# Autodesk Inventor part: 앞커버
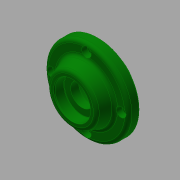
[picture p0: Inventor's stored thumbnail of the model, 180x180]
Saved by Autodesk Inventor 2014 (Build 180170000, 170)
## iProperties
Created: 2017-08
Part Number: 앞커버
Material: 알루미늄 6061
Document SubType Name: Modeling
Designer: mduedu
Density: 1 g/cm^3
Appearance: Dark Green
Author: mduedu
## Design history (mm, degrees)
sketch "스케치1"
  geometry: C1 r 35 at (0, 0); 1 further point
  constraints: 1 centre point, 1 coincident
  dimensions: "d0" = 70 diameter of C1
extrude "돌출1" new body sketch "스케치1" distance "d1" = 10; taper "d2" = 0 deg
sketch "스케치2"
  geometry: C1 r 24 at (0, 0); 1 further point
  constraints: 1 centre point, 1 coincident
  dimensions: "d3" = 48 diameter of C1
node "작업 평면1"
sketch "스케치3"
  geometry: C1 r 20 at (0, 0); 1 further point
  constraints: 1 centre point, 1 coincident
  dimensions: "d5" = 40 diameter of C1
feature "로프트1" sketch "스케치3" dims "d6" = 0, "d7" = 90 deg, "d8" = 0, "d9" = 90 deg
sketch "스케치4"
  geometry: C1 r 24 at (0, 0) reference; 1 further point
extrude "돌출2" join sketch "스케치4" distance "d10" = 8; taper "d11" = 0 deg
hole "구멍1" diameter "d14" = 40; stored, may be unused: countersink angle "d18" = 90 deg, drill point angle "d20" = 0 deg; dims "d12" = 10, "d13" = 10, "d15" = 6, "d16" = 4, "d17" = 2, "d19" = 12
hole "구멍2" diameter "d23" = 34; stored, may be unused: countersink angle "d27" = 90 deg, drill point angle "d29" = 0 deg; dims "d21" = 10, "d22" = 10, "d24" = 6, "d25" = 4, "d26" = 2, "d28" = 3
hole "구멍3" diameter "d32" = 19; stored, may be unused: countersink angle "d36" = 90 deg, drill point angle "d38" = 0 deg; dims "d30" = 10, "d31" = 10, "d33" = 6, "d34" = 4, "d35" = 2, "d37" = 3
chamfer "모따기1" distance "d39" = 1; stored, may be unused: second distance "d40" = 2, angle "d41" = 45 deg
sketch "스케치5"
  geometry: C1 r 15 at (0, 0); 1 further point
  constraints: 1 centre point, 1 coincident
  dimensions: "d42" = 30 diameter of C1
extrude "돌출3" cut sketch "스케치5" distance "d43" = 8.3; taper "d44" = 0 deg
chamfer "모따기2" distance "d47" = 0.8; stored, may be unused: second distance "d48" = 2, angle "d49" = 30 deg
fillet "모깎기1" dims "d50" = 0.3
fillet "모깎기2" dims "d51" = 0.3
fillet "모깎기3" dims "d52" = 3
sketch "스케치6" dims "d53" = 58
  geometry: 6 further points
  constraints: 2 vertical alignment, 1 coincident, 7 other
  dimensions: "d56" = 360 deg dimension on point (0, 0) point (0, 29) (derived)
sketch "스케치9"
  geometry: 4 further points
  constraints: 4 other
hole "구멍6" sketch "스케치9" at (-29, 0), (0, -29), (29, 0), (0, 29) diameter "d72" = 4.5; stored, may be unused: countersink angle "d76" = 90 deg, drill point angle "d78" = 0 deg; dims "d73" = 6, "d74" = 8, "d75" = 4.6, "d77" = 8
fillet "모깎기4" dims "d79" = 3
fillet "모깎기5" dims "d80" = 3
fillet "모깎기6" dims "d81" = 3
chamfer "모따기3" distance "d82" = 1; stored, may be unused: second distance "d83" = 2, angle "d84" = 30 deg
node "솔리드1"
other parameters: "d4" = 12
